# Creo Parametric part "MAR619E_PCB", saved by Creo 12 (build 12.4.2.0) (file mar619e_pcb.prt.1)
Units: Custom; MM, KILOGRAM, SECS

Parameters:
  PTC_WM_ITERATION = "0"
  PTC_WM_VERSION = "-.0"
  PTC_WM_LIFECYCLE_STATE = "In Work"
  PTC_WM_LIFECYCLE = "MO_CADDocument"
  PTC_WM_CREATED_BY = "Maximilian Roepper (Z0017RMS: MO)"
  PTC_WM_CREATED_ON = "18-Sep-26 11:36:42 AM"
  PTC_WM_MODIFIED_BY = "Maximilian Roepper (Z0017RMS: MO)"
  PTC_WM_MODIFIED_ON = "18-Sep-26 11:36:46 AM"
  PDMLINKNUMBER = "PDM000071454784"
  PTC_WM_NAME = "mar619e_pcb.prt"
  PTC_WM_NUMBER = "PDM000071454784"

Other parameters: WEIGHT, WEIGHT_FACTOR, WEIGHT_ADD, _MASS_TEMP, _DIFF_TEMP, MC_ERRORS, SUPPLIER

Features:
  1. coordinate system
  2. datum plane "PRT_YZ"
  3. datum plane "PRT_XY"
  4. datum plane "PRT_XZ"
  5. coordinate system
  6. datum axis
  7. datum axis
  8. datum axis
  9. coordinate system
  10. imported feature
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
Other named items: PRT, SIEMENS_MO, DRW_VIEW_ORG, PRT_X, PRT_Y, PRT_Z, CS0, ROUGH_GROB

Layers: 00_STD_CSYS-KSYS, 01_STD_PLANES-EBENEN, 02_STD_AXES-ACHSEN, 03_STD_CSYS-KSYS, 24_IMPORT_FEAT-IMPORT_KE

Surfaces: 112 cylinder, 13 plane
